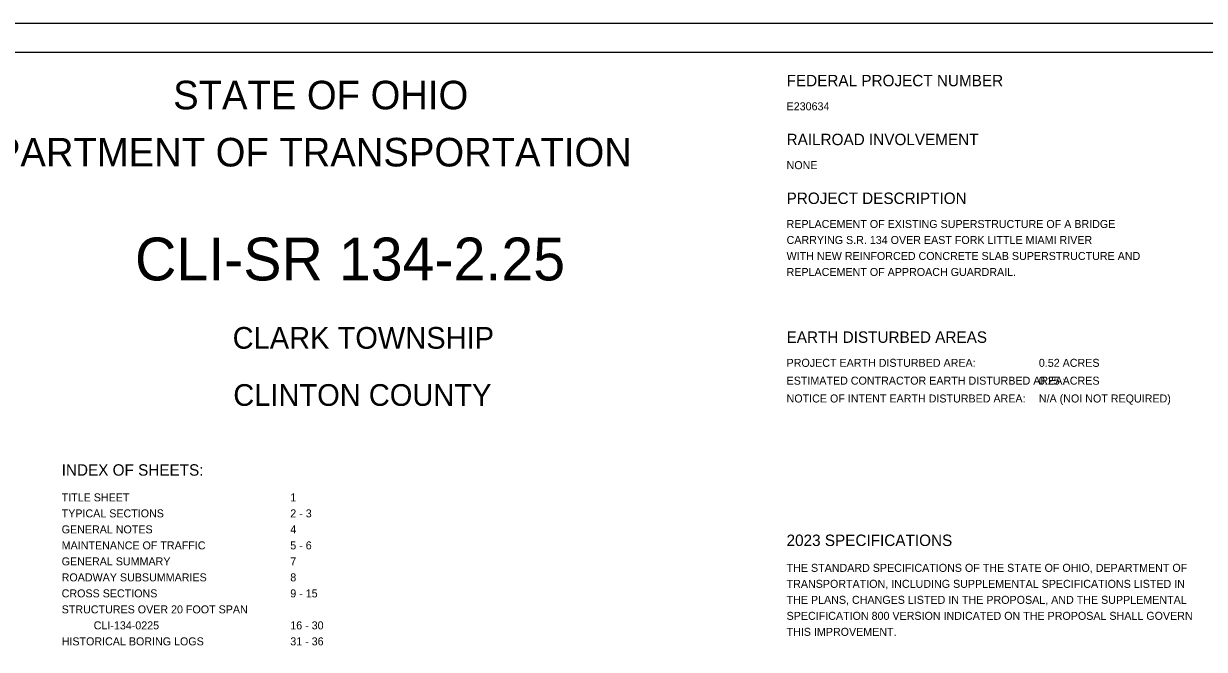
# Model space of a CAD drawing. Extents: x 0 to 48.6, y 0 to 22.
# Drawn here: x 11.18 to 31.84, y 11.05 to 22 of the extents above; entities that cross this region are included whole.
import ezdxf

# ---------------------------------------------------------------- set-up
doc = ezdxf.new("R2010")
doc.units = 0
for name, color, linetype in [('SH_Border', 7, 'Continuous'), ('SH_Cut_Line', 7, 'Continuous'), ('SH_Text', 7, 'Continuous')]:
    doc.layers.add(name, color=color, linetype=linetype)

msp = doc.modelspace()

# ---------------------------------------------------------------- linework, layer by layer
at = {"layer": 'SH_Border'}
msp.add_lwpolyline([(1.5, 21.5), (33.5, 21.5), (33.5, 0.5), (1.5, 0.5)], close=True, dxfattribs=at)
at = {"layer": 'SH_Cut_Line'}
msp.add_lwpolyline([(0, 0), (34, 0), (34, 22), (0, 22)], close=True, dxfattribs=at)

# ---------------------------------------------------------------- texts
at = {"layer": 'SH_Text'}
for s, height, p in [('FEDERAL PROJECT NUMBER', 0.2, (24.528, 20.903)), ('STATE OF OHIO', 0.5, (13.795, 20.5)), ('E230634   ', 0.14, (24.528, 20.483)), ('RAILROAD INVOLVEMENT', 0.2, (24.528, 19.873)), ('DEPARTMENT OF TRANSPORTATION', 0.5, (9.747, 19.5)), ('NONE                ', 0.14, (24.528, 19.453)), ('PROJECT DESCRIPTION', 0.2, (24.528, 18.843)), ('REPLACEMENT OF EXISTING SUPERSTRUCTURE OF A BRIDGE      ', 0.14, (24.528, 18.423)), ('CLI-SR 134-2.25', 0.75, (13.127, 17.505)), ('CARRYING S.R. 134 OVER EAST FORK LITTLE MIAMI RIVER     ', 0.14, (24.528, 18.143)), ('WITH NEW REINFORCED CONCRETE SLAB SUPERSTRUCTURE AND    ', 0.14, (24.528, 17.863)), ('REPLACEMENT OF APPROACH GUARDRAIL.                      ', 0.14, (24.528, 17.583)), ('   CLARK TOWNSHIP   ', 0.38, (14.412, 16.31)), ('EARTH DISTURBED AREAS', 0.2, (24.528, 16.413)), ('PROJECT EARTH DISTURBED AREA:', 0.14, (24.528, 15.993)), ('0.52 ACRES', 0.14, (28.942, 15.993)), ('ESTIMATED CONTRACTOR EARTH DISTURBED AREA:', 0.14, (24.528, 15.681)), ('0.25 ACRES', 0.14, (28.942, 15.681)), ('   CLINTON COUNTY   ', 0.38, (14.423, 15.31)), ('NOTICE OF INTENT EARTH DISTURBED AREA:', 0.14, (24.528, 15.369)), ('N/A (NOI NOT REQUIRED)', 0.14, (28.942, 15.369)), ('INDEX OF SHEETS:', 0.2, (11.844, 14.088)), ('TITLE SHEET                         ', 0.14, (11.844, 13.638)), ('1      ', 0.14, (15.844, 13.638)), ('TYPICAL SECTIONS                    ', 0.14, (11.844, 13.358)), ('2 - 3  ', 0.14, (15.844, 13.358)), ('GENERAL NOTES                       ', 0.14, (11.844, 13.078)), ('4      ', 0.14, (15.844, 13.078)), ('2023 SPECIFICATIONS', 0.2, (24.528, 12.857)), ('MAINTENANCE OF TRAFFIC              ', 0.14, (11.844, 12.798)), ('5 - 6  ', 0.14, (15.844, 12.798)), ('GENERAL SUMMARY                     ', 0.14, (11.844, 12.518)), ('7      ', 0.14, (15.844, 12.518)), ('THE STANDARD SPECIFICATIONS OF THE STATE OF OHIO, DEPARTMENT OF', 0.14, (24.528, 12.405)), ('ROADWAY SUBSUMMARIES                ', 0.14, (11.844, 12.238)), ('8      ', 0.14, (15.844, 12.238)), ('TRANSPORTATION, INCLUDING SUPPLEMENTAL SPECIFICATIONS LISTED IN', 0.14, (24.528, 12.125)), ('CROSS SECTIONS                      ', 0.14, (11.844, 11.958)), ('9 - 15 ', 0.14, (15.844, 11.958)), ('THE PLANS, CHANGES LISTED IN THE PROPOSAL, AND THE SUPPLEMENTAL', 0.14, (24.528, 11.845)), ('STRUCTURES OVER 20 FOOT SPAN        ', 0.14, (11.844, 11.678)), ('SPECIFICATION 800 VERSION INDICATED ON THE PROPOSAL SHALL GOVERN', 0.14, (24.528, 11.565)), ('CLI-134-0225 ', 0.14, (12.404, 11.398)), ('16 - 30', 0.14, (15.844, 11.398)), ('THIS IMPROVEMENT.', 0.14, (24.528, 11.285)), ('HISTORICAL BORING LOGS              ', 0.14, (11.844, 11.118)), ('31 - 36', 0.14, (15.844, 11.118))]:
    msp.add_text(s, height=height, dxfattribs=at).set_placement(p)

doc.saveas('drawing.dxf')
